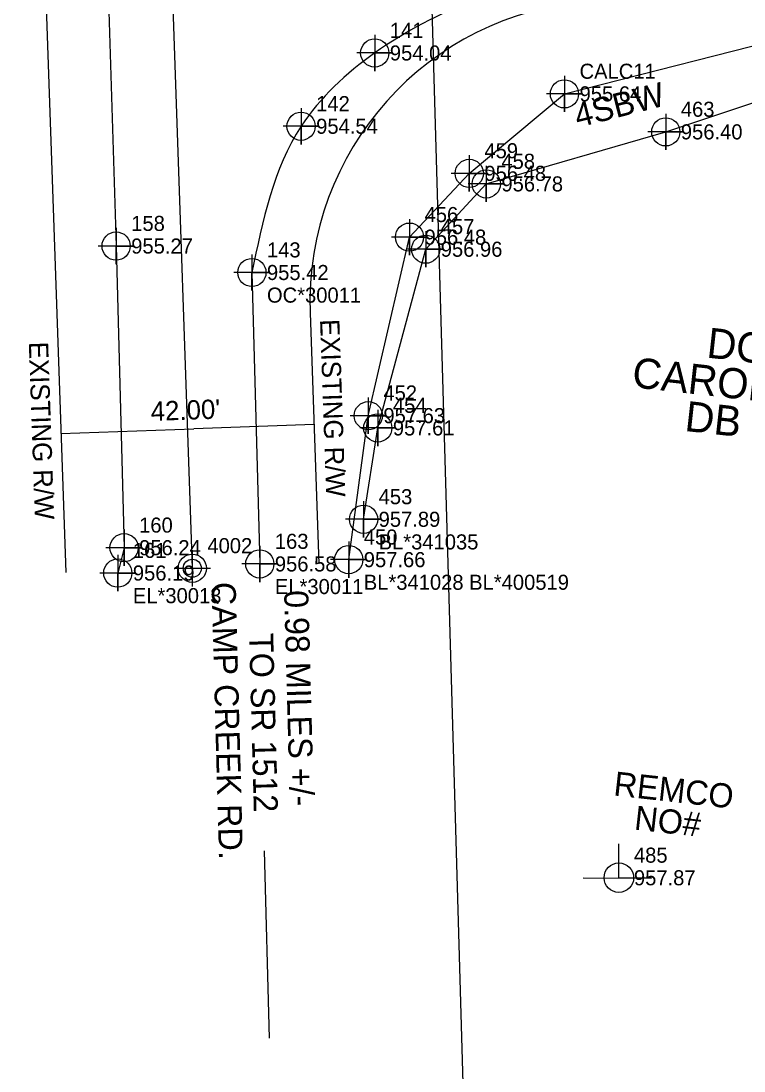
# Model space of a CAD drawing. Extents: x 1150279 to 1151282, y 655434 to 657999.
# Drawn here: x 1150547.5 to 1150667.5, y 656934.2 to 657108.3 of the extents above; entities that cross this region are included whole.
import ezdxf

# ---------------------------------------------------------------- set-up
doc = ezdxf.new("R2010")
doc.units = 0
for name, color, linetype in [('COGO Default Chain', 7, 'Continuous'), ('Cogo Default Point CELL', 7, 'Continuous'), ('COGO Default Point Number', 7, 'Continuous'), ('Exist Horizontal Alignment', 7, 'Continuous'), ('Exist Horizontal Alignment Station Label', 7, 'Continuous'), ('Exist Other Culture Fence Line', 7, 'Continuous'), ('Exist Other Culture Fence Line Cogo Comment', 7, 'Continuous'), ('Exist Other Culture Fence Line Cogo Elevation', 7, 'Continuous'), ('Exist Other Culture Fence Line Cogo Number', 7, 'Continuous'), ('Exist Other Culture Fence Line Cogo Point CELL', 7, 'Continuous'), ('Exist Other Culture Fence Line Text', 7, 'Continuous'), ('Exist Property Deed Book Text', 7, 'Continuous'), ('Exist Property Owner Text', 7, 'Continuous'), ('Exist Right of Way Line', 7, 'Continuous'), ('Exist Right of Way Line Text', 7, 'Continuous'), ('Exist Right of Way Width CELL', 7, 'Continuous'), ('Exist Roads EOP', 7, 'Continuous'), ('Exist Roads EOP Cogo Comment', 7, 'Continuous'), ('Exist Roads EOP Cogo Elevation', 7, 'Continuous'), ('Exist Roads EOP Cogo Number', 7, 'Continuous'), ('Exist Roads EOP Cogo Point CELL', 7, 'Continuous'), ('Exist Roads EOP Leader', 7, 'Continuous'), ('Exist Roads EOP Text', 7, 'Continuous'), ('Exist Utilities Power Joint Use Telephone CELL', 7, 'Continuous'), ('Exist Utilities Power Joint Use Telephone Cogo Elevation', 7, 'Continuous'), ('Exist Utilities Power Joint Use Telephone Cogo Number', 7, 'Continuous'), ('Exist Utilities Power Joint Use Telephone Text', 7, 'Continuous')]:
    doc.layers.add(name, color=color, linetype=linetype)

msp = doc.modelspace()

# ---------------------------------------------------------------- linework, layer by layer
at = {"layer": 'COGO Default Chain'}
for p, q in [((1150568.54, 657231.15), (1150575.96, 657017.52)), ((1150663.4, 655450.47), (1150614.76, 657145.26))]:
    msp.add_line(p, q, dxfattribs=at)
at = {"layer": 'Cogo Default Point CELL'}
for points in [[(1150575.96, 657020.52), (1150575.96, 657017.52)], [(1150572.96, 657017.52), (1150575.96, 657017.52)], [(1150575.96, 657017.52), (1150578.96, 657017.52)], [(1150575.96, 657017.52), (1150575.96, 657014.52)]]:
    msp.add_lwpolyline(points, dxfattribs=at)
msp.add_circle((1150575.96, 657017.52), 2.34, dxfattribs=at)
at = {"layer": 'Exist Horizontal Alignment'}
msp.add_line((1150568.54, 657231.15), (1150575.96, 657017.52), dxfattribs=at)
at = {"layer": 'Exist Horizontal Alignment Station Label'}
msp.add_circle((1150575.96, 657017.52), 1.5, dxfattribs=at)
at = {"layer": 'Exist Other Culture Fence Line'}
for points in [[(1150601.9, 657018.95), (1150605.15, 657042.82), (1150611.98, 657072.42), (1150621.9, 657083), (1150637.68, 657096.18), (1150678.11, 657106.44)], [(1150604.36, 657025.64), (1150606.72, 657040.79), (1150614.66, 657070.42), (1150624.72, 657081.25), (1150654.48, 657089.88), (1150677.88, 657097.66), (1150678.26, 657106.74)]]:
    msp.add_lwpolyline(points, dxfattribs=at)
at = {"layer": 'Exist Other Culture Fence Line Cogo Point CELL'}
for points in [[(1150637.68, 657099.18), (1150637.68, 657093.18), (1150637.68, 657096.18), (1150640.68, 657096.18), (1150634.68, 657096.18)], [(1150654.48, 657092.88), (1150654.48, 657086.88), (1150654.48, 657089.88), (1150657.48, 657089.88), (1150651.48, 657089.88)], [(1150621.9, 657086), (1150621.9, 657080), (1150621.9, 657083), (1150624.9, 657083), (1150618.9, 657083)], [(1150624.72, 657084.25), (1150624.72, 657078.25), (1150624.72, 657081.25), (1150627.72, 657081.25), (1150621.72, 657081.25)], [(1150611.98, 657075.42), (1150611.98, 657069.42), (1150611.98, 657072.42), (1150614.98, 657072.42), (1150608.98, 657072.42)], [(1150614.66, 657073.42), (1150614.66, 657067.42), (1150614.66, 657070.42), (1150617.66, 657070.42), (1150611.66, 657070.42)], [(1150605.15, 657045.82), (1150605.15, 657039.82), (1150605.15, 657042.82), (1150608.15, 657042.82), (1150602.15, 657042.82)], [(1150606.72, 657043.79), (1150606.72, 657037.79), (1150606.72, 657040.79), (1150609.72, 657040.79), (1150603.72, 657040.79)], [(1150604.36, 657028.64), (1150604.36, 657022.64), (1150604.36, 657025.64), (1150607.36, 657025.64), (1150601.36, 657025.64)], [(1150601.9, 657021.95), (1150601.9, 657015.95), (1150601.9, 657018.95), (1150604.9, 657018.95), (1150598.9, 657018.95)]]:
    msp.add_lwpolyline(points, dxfattribs=at)
for centre in [(1150637.68, 657096.18), (1150654.48, 657089.88), (1150621.9, 657083), (1150624.72, 657081.25), (1150611.98, 657072.42), (1150614.66, 657070.42), (1150605.15, 657042.82), (1150606.72, 657040.79), (1150604.36, 657025.64), (1150601.9, 657018.95)]:
    msp.add_circle(centre, 2.34, dxfattribs=at)
at = {"layer": 'Exist Right of Way Line'}
for p, q in [((1150547.55, 657230.42), (1150554.98, 657016.79)), ((1150595.5, 657059.88), (1150596.95, 657018.25))]:
    msp.add_line(p, q, dxfattribs=at)
msp.add_arc((1150645.47, 657061.62), 50, 94.3102, 181.9914, dxfattribs=at)
at = {"layer": 'Exist Right of Way Width CELL'}
for p in [(1150596.15, 657041.35), (1150554.17, 657039.89)]:
    msp.add_line(p, (1150576.2, 657040.66), dxfattribs=at)
at = {"layer": 'Exist Roads EOP'}
msp.add_line((1150585.84, 657066.56), (1150587.15, 657018.24), dxfattribs=at)
msp.add_lwpolyline([(1150555.6, 657230.84), (1150557.81, 657218.94), (1150559.89, 657167.47), (1150561.73, 657122.25), (1150563.33, 657070.95), (1150564.64, 657020.93), (1150563.6, 657016.73)], dxfattribs=at)
msp.add_spline([(1150646.28, 657116.94), (1150622.67, 657111.56), (1150606.22, 657102.96), (1150594, 657090.81), (1150585.84, 657066.56)], degree=3, dxfattribs=at)
at = {"layer": 'Exist Roads EOP Cogo Point CELL'}
for points in [[(1150606.22, 657105.96), (1150606.22, 657099.96), (1150606.22, 657102.96), (1150609.22, 657102.96), (1150603.22, 657102.96)], [(1150594, 657093.81), (1150594, 657087.81), (1150594, 657090.81), (1150597, 657090.81), (1150591, 657090.81)], [(1150563.33, 657073.95), (1150563.33, 657067.95), (1150563.33, 657070.95), (1150566.33, 657070.95), (1150560.33, 657070.95)], [(1150585.84, 657069.56), (1150585.84, 657063.56), (1150585.84, 657066.56), (1150588.84, 657066.56), (1150582.84, 657066.56)], [(1150564.64, 657023.93), (1150564.64, 657017.93), (1150564.64, 657020.93), (1150567.64, 657020.93), (1150561.64, 657020.93)], [(1150587.15, 657021.24), (1150587.15, 657015.24), (1150587.15, 657018.24), (1150590.15, 657018.24), (1150584.15, 657018.24)], [(1150563.6, 657019.73), (1150563.6, 657013.73), (1150563.6, 657016.73), (1150566.6, 657016.73), (1150560.6, 657016.73)]]:
    msp.add_lwpolyline(points, dxfattribs=at)
for centre in [(1150606.22, 657102.96), (1150594, 657090.81), (1150563.33, 657070.95), (1150585.84, 657066.56), (1150564.64, 657020.93), (1150587.15, 657018.24), (1150563.6, 657016.73)]:
    msp.add_circle(centre, 2.34, dxfattribs=at)
at = {"layer": 'Exist Roads EOP Leader'}
msp.add_line((1150588.77, 656939.61), (1150587.95, 656970.64), dxfattribs=at)
at = {"layer": 'Exist Utilities Power Joint Use Telephone CELL'}
msp.add_line((1150646.7, 656966.2), (1150646.7, 656966.2), dxfattribs=at)
msp.add_lwpolyline([(1150640.76, 656966.2), (1150652.1, 656966.16), (1150646.7, 656966.18), (1150646.7, 656971.83)], dxfattribs=at)
msp.add_circle((1150646.7, 656966.21), 2.45, dxfattribs=at)

# ---------------------------------------------------------------- texts
at = {"layer": 'COGO Default Point Number'}
msp.add_text('4002', height=2.5, dxfattribs=at).set_placement((1150578.46, 657020.02))
at = {"layer": 'Exist Other Culture Fence Line Cogo Comment'}
for s, p in [('BL*341035', (1150606.86, 657020.64)), ('BL*341028 BL*400519', (1150604.4, 657013.95))]:
    msp.add_text(s, height=2.5, dxfattribs=at).set_placement(p)
at = {"layer": 'Exist Other Culture Fence Line Cogo Elevation'}
for s, p in [('955.64', (1150640.18, 657094.93)), ('956.40', (1150656.98, 657088.63)), ('956.48', (1150624.4, 657081.75)), ('956.78', (1150627.22, 657080)), ('956.48', (1150614.48, 657071.17)), ('956.96', (1150617.16, 657069.17)), ('957.63', (1150607.65, 657041.58)), ('957.61', (1150609.22, 657039.54)), ('957.89', (1150606.86, 657024.39)), ('957.66', (1150604.4, 657017.7))]:
    msp.add_text(s, height=2.5, dxfattribs=at).set_placement(p)
at = {"layer": 'Exist Other Culture Fence Line Cogo Number'}
for s, p in [('CALC11', (1150640.18, 657098.68)), ('463', (1150656.98, 657092.38)), ('459', (1150624.4, 657085.5)), ('458', (1150627.22, 657083.75)), ('456', (1150614.48, 657074.92)), ('457', (1150617.16, 657072.92)), ('452', (1150607.65, 657045.33)), ('454', (1150609.22, 657043.29)), ('453', (1150606.86, 657028.14)), ('450', (1150604.4, 657021.45))]:
    msp.add_text(s, height=2.5, dxfattribs=at).set_placement(p)
at = {"layer": 'Exist Other Culture Fence Line Text'}
msp.add_text('4SBW', height=4, rotation=14.2331, dxfattribs=at).set_placement((1150639.9, 657090.56))
at = {"layer": 'Exist Property Deed Book Text'}
msp.add_text('DB 748 PG 810', height=5, rotation=353.6867, dxfattribs=at).set_placement((1150657.48, 657040.3))
at = {"layer": 'Exist Property Owner Text'}
for s, p in [('DOUGLAS H. &', (1150661.13, 657052.47)), ('CAROL S. NETHAWAY', (1150648.74, 657047.56))]:
    msp.add_text(s, height=5, rotation=353.6867, dxfattribs=at).set_placement(p)
at = {"layer": 'Exist Right of Way Line Text'}
for p in [(1150597.14, 657058.77), (1150548.84, 657055.02)]:
    msp.add_text('EXISTING R/W', height=3.2, rotation=271.9914, dxfattribs=at).set_placement(p)
at = {"layer": 'Exist Right of Way Width CELL'}
msp.add_text("42.00'", height=3.2, rotation=1.9914, dxfattribs=at).set_placement((1150569.12, 657041.94))
at = {"layer": 'Exist Roads EOP Cogo Comment'}
for s, p in [('OC*30011', (1150588.34, 657061.56)), ('EL*30011', (1150589.65, 657013.24)), ('EL*30013', (1150566.1, 657011.73))]:
    msp.add_text(s, height=2.5, dxfattribs=at).set_placement(p)
at = {"layer": 'Exist Roads EOP Cogo Elevation'}
for s, p in [('954.04', (1150608.72, 657101.71)), ('954.54', (1150596.5, 657089.56)), ('955.27', (1150565.83, 657069.7)), ('955.42', (1150588.34, 657065.31)), ('956.24', (1150567.14, 657019.68)), ('956.58', (1150589.65, 657016.99)), ('956.19', (1150566.1, 657015.48))]:
    msp.add_text(s, height=2.5, dxfattribs=at).set_placement(p)
at = {"layer": 'Exist Roads EOP Cogo Number'}
for s, p in [('141', (1150608.72, 657105.46)), ('142', (1150596.5, 657093.31)), ('158', (1150565.83, 657073.45)), ('143', (1150588.34, 657069.06)), ('160', (1150567.14, 657023.43)), ('163', (1150589.65, 657020.74)), ('161', (1150566.1, 657019.23))]:
    msp.add_text(s, height=2.5, dxfattribs=at).set_placement(p)
at = {"layer": 'Exist Roads EOP Text'}
for s, p in [('CAMP CREEK RD.', (1150579.14, 657015.19)), ('0.98 MILES +/-', (1150591.18, 657013.83)), ('TO SR 1512', (1150585.37, 657006.72))]:
    msp.add_text(s, height=4, rotation=271.5458, dxfattribs=at).set_placement(p)
at = {"layer": 'Exist Utilities Power Joint Use Telephone Cogo Elevation'}
msp.add_text('957.87', height=2.5, dxfattribs=at).set_placement((1150649.2, 656964.95))
at = {"layer": 'Exist Utilities Power Joint Use Telephone Cogo Number'}
msp.add_text('485', height=2.5, dxfattribs=at).set_placement((1150649.2, 656968.7))
at = {"layer": 'Exist Utilities Power Joint Use Telephone Text'}
for s, p in [('REMCO', (1150645.7, 656979.86)), ('NO#', (1150649.13, 656974.2))]:
    msp.add_text(s, height=4, rotation=353.6867, dxfattribs=at).set_placement(p)

doc.saveas('drawing.dxf')
